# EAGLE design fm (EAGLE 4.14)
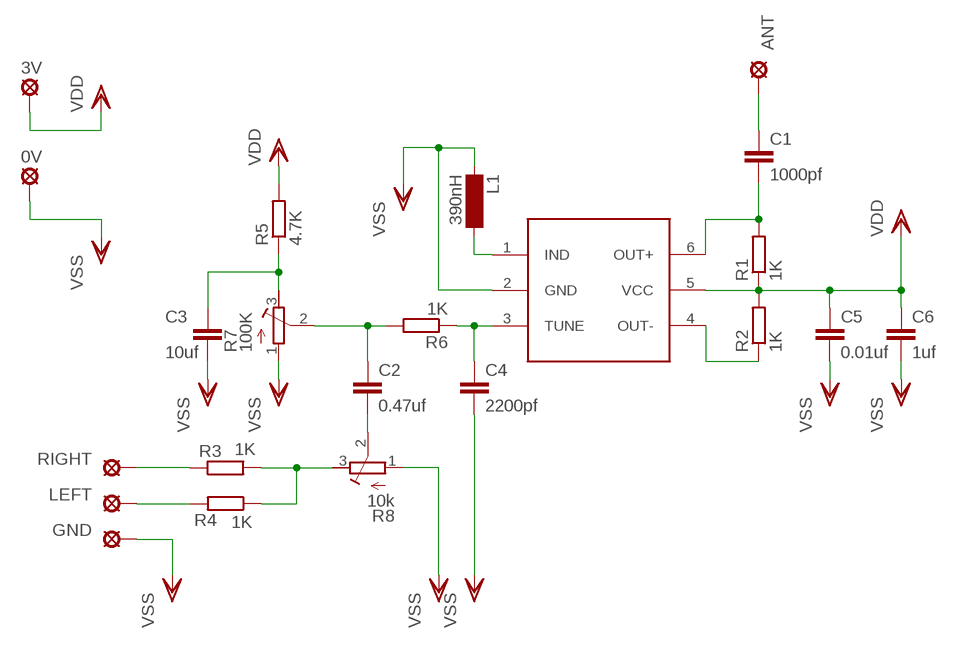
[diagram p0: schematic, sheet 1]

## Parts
0V  SE14  [SE14]
3V  SE14  [SE14]
ANT  SE14  [SE14]
C1  1000pf  C-EUC0603  [C0603]
C2  0.47uf  C-EUC0805  [C0805]
C3  10uf  C-EUC0805  [C0805]
C4  2200pf  C-EUC0603  [C0603]
C5  0.01uf  C-EUC0805  [C0805]
C6  1uf  C-EUC0805  [C0805]
GND  SE14  [SE14]
IC1  MAX260X  [SOT23-6]
L1  390nH  SM-1206  [SM-1206]
LEFT  SE14  [SE14]
R1  1K  R-EU_M0805  [M0805]
R2  1K  R-EU_M0805  [M0805]
R3  1K  R-EU_M0805  [M0805]
R4  1K  R-EU_M0805  [M0805]
R5  4.7K  R-EU_M0805  [M0805]
R6  1K  R-EU_M0805  [M0805]
R7  100K  R-TRIMM3103  [RTRIM3103]
R8  10k  R-TRIMM3103  [RTRIM3103]
RIGHT  SE14  [SE14]

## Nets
N$1: R3.2 R4.1 R8.3(A)
N$2: IC1.4(OUT-) R2.1
N$3: C1.2 IC1.6(OUT+) R1.2
N$4: R3.1 RIGHT.MP
N$5: LEFT.MP R4.2
N$6: C3.1 R5.1 R7.3(A)
N$7: ANT.MP C1.1
N$8: C4.1 IC1.3(TUNE) R6.1
N$9: C2.2 R8.2(S)
N$10: C2.1 R6.2 R7.2(S)
N$12: IC1.1(IND) L1.2
VDD: 3V.MP C5.1 C6.1 IC1.5(VCC) R1.1 R2.2 R5.2
VSS: 0V.MP C3.2 C4.2 C5.2 C6.2 GND.MP IC1.2(GND) L1.1 R7.1(E) R8.1(E)

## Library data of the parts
0V 3V ANT GND LEFT RIGHT = solpad:SE14: SOLDER PAD
C1-C6 = rcl:C-EU: CAPACITOR, European symbol
IC1 = max260X:MAX260X
L1 = inductor-neosid:SM-1206: INDUCTOR
R1-R6 = rcl:R-EU_: RESISTOR, European symbol
R7 R8 = rcl:R-TRIMM: Trimm resistor

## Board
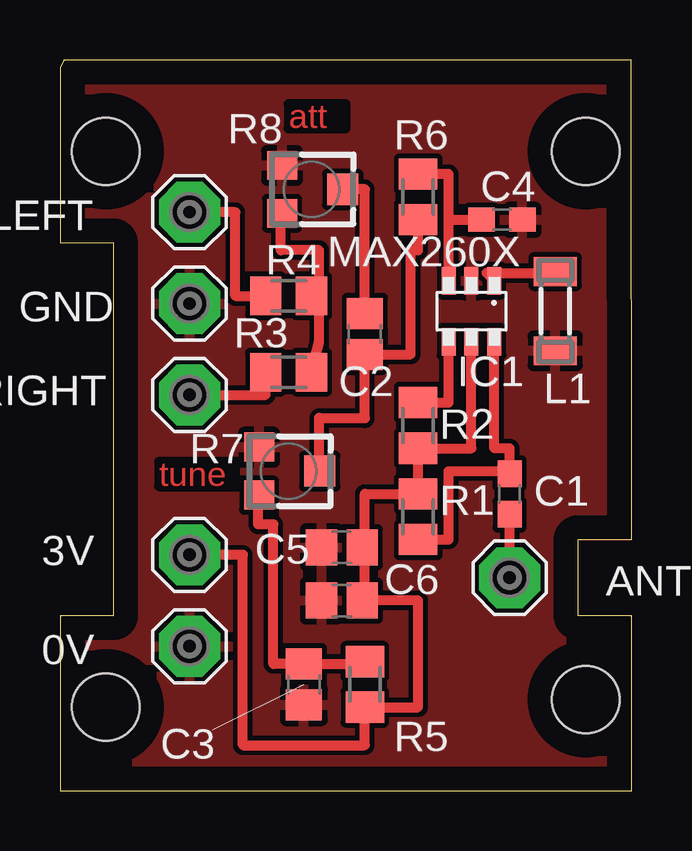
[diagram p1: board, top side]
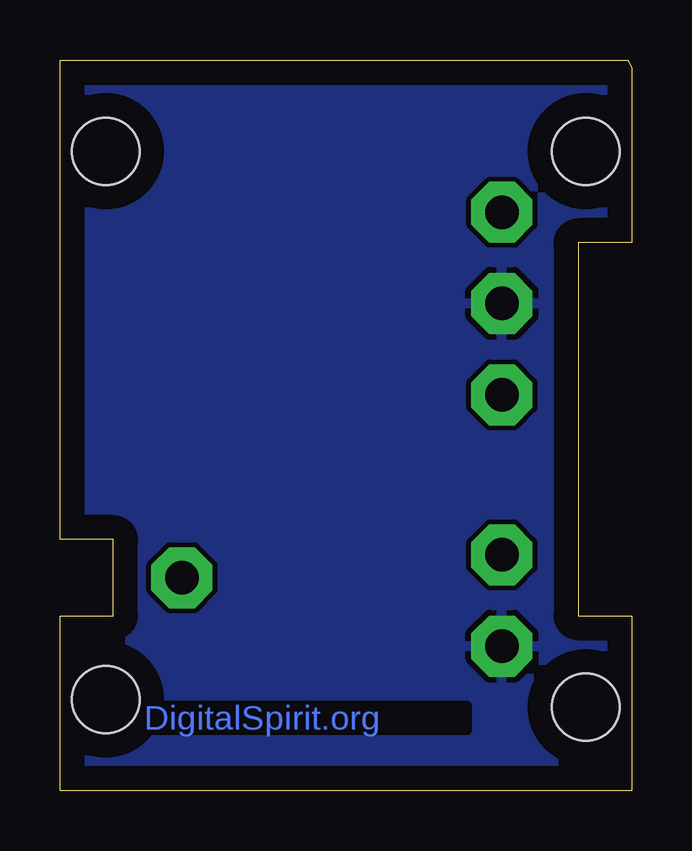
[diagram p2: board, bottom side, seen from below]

Size 23.81 x 30.47 mm. Coordinates in mm from the lower left corner, seen from the top.
Outline: 23.81,0 23.81,7.3 21.59,7.3 21.59,10.47 23.81,10.47 23.81,30.47 0.17,30.47 0,30.16 0,22.86 2.22,22.86 2.22,7.3 0,7.3 0,0 23.81,0
Copper layers (1*16): Top 0.035mm / dielectric 1.5mm / Bottom 0.035mm
Design rules "default": minimum track width 10mil, minimum drill 24mil, track to track 8mil, track to pad 8mil, pad to pad 8mil, via to via 8mil, smd to smd 8mil, copper to edge 40mil, drill to drill 8mil, minimum pad ring 10mil, minimum via ring 8mil, stop-mask expansion 4mil, vias tented up to drill 0mil, thermal gap 10mil
Holes 2.8 mm at 1.91,3.49 21.91,3.8 21.91,26.66 1.91,26.66

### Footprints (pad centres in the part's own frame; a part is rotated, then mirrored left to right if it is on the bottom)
SE14 = drill 1.397 pad 2.54 octagon: MP 0,0
C0603 = smd 1.1 x 1: 1 -0.85,0; 2 0.85,0
C0805 = smd 1.3 x 1.5: 1 -0.85,0; 2 0.85,0
SOT23-6 = smd 0.584 x 1.143: 1 -0.953,-1.27; 2 0,-1.27; 3 0.953,-1.27; 4 0.953,1.27; 5 0,1.27; 6 -0.953,1.27
SM-1206 = smd 1.2 x 1.8: 1 -1.65,0; 2 1.65,0
M0805 = smd 1.3 x 1.6: 1 -0.95,0; 2 0.95,0
RTRIM3103 = smd 1.2 x 1.25: 1 -1,-1.225; 3 1,-1.225 | smd 1.3 x 1.3: 2 0,1.3

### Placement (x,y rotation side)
0V  5.4,6.03 0 top
3V  5.4,9.84 0 top
ANT  18.73,8.89 0 top
C1  18.73,12.38 90 top
C2  12.7,19.04 90 top
C3  10.16,4.44 270 top
C4  18.42,23.81 0 top
C5  11.75,10.16 180 top
C6  11.75,7.93 180 top
GND  5.4,20.31 0 top
IC1  17.15,20 180 top
L1  20.64,20 90 top
LEFT  5.4,24.12 0 top
R1  14.92,11.43 270 top
R2  14.92,15.24 270 top
R3  9.53,17.46 0 top
R4  9.53,20.63 180 top
R5  12.7,4.44 270 top
R6  14.92,24.76 270 top
R7  9.53,13.33 270 top
R8  10.48,25.08 270 top
RIGHT  5.4,16.5 0 top

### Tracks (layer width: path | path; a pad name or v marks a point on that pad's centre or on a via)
N$1
  Top 0.406: R3.2 10.79,18.73 10.79,20.31 R4.1 10.79,20.63 10.79,22.54 9.21,22.54 9.21,24.08 | 9.21,24.08 9.21,24.12 | 9.21,24.08 R8.3
N$2
  Top 0.406: R2.1 16.19,16.18 IC1.4
N$3
  Top 0.406: IC1.6 18.1,14.28 18.73,14.28 18.73,13.33 | R1.2 16.19,10.48 | 16.19,10.48 16.19,10.47 | 16.19,10.48 16.19,13.33 18.73,13.33 | 18.73,13.33 C1.2
N$4
  Top 0.406: R3.1 8.57,16.5 RIGHT.MP
N$5
  Top 0.406: LEFT.MP 7.3,24.12 7.3,20.63 R4.2
N$6
  Top 0.406: 8.26,12.01 8.26,12.06 | 8.26,12.01 R7.3 | 8.26,12.01 8.26,11.11 8.89,11.11 8.89,5.29 C3.1 12.7,5.29 | 12.7,5.29 12.7,5.08 | 12.7,5.29 R5.1
N$7
  Top 0.406: ANT.MP C1.1
N$8
  Top 0.406: R6.1 16.19,25.71 16.19,23.81 | IC1.3 16.19,23.81 | 16.19,23.81 C4.1
N$9
  Top 0.406: C2.2 12.7,25.08 R8.2 11.75,25.08
N$10
  Top 0.406: 12.7,15.55 12.7,15.52 | 12.7,15.55 C2.1 14.61,18.2 14.61,22.54 14.92,22.54 R6.2 | R7.2 10.79,13.33 10.79,15.55 12.7,15.55
N$12
  Top 0.406: IC1.1 17.78,21.58 20,21.58 L1.2
VDD
  Top 0.406: 3V.MP 7.62,9.84 7.62,1.9 12.7,1.9 R5.2 | 12.7,10.16 C5.1 | 12.7,10.16 12.7,7.93 C6.1 14.92,7.93 14.92,3.49 R5.2 | R5.2 | 12.7,10.16 12.7,12.38 R1.1 R2.2 | IC1.5 17.15,14.28 R2.2 | R2.2
VSS
  pour Top: 0.32,30.16 23.5,30.16 23.5,10.79 21.27,10.79 21.27,6.98 23.5,6.98 23.5,0.31 0.32,0.31 0.32,6.98 2.54,6.98 2.54,23.17 0.32,23.17
  pour Bottom: 0.32,30.16 23.5,30.16 23.5,10.79 21.27,10.79 21.27,6.98 23.5,6.98 23.5,0.31 0.32,0.31 0.32,6.98 2.54,6.98 2.54,23.17 0.32,23.17

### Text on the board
Top: att | tune
Bottom: DigitalSpirit.org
